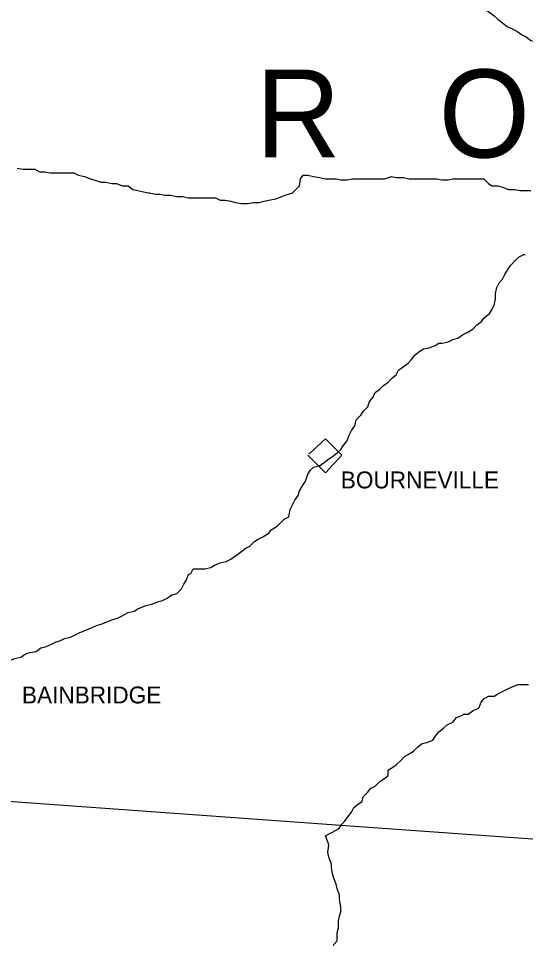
# Model space of a CAD drawing. Extents: x 0 to 40.2, y 0 to 22.
# Drawn here: x 5.119 to 5.704, y 18.331 to 19.393 of the extents above; entities that cross this region are included whole.
import ezdxf

# ---------------------------------------------------------------- set-up
doc = ezdxf.new("R2010")
doc.units = 0
doc.layers.add('Default', color=7, linetype='Continuous')
doc.layers.add('TR_Turning_Path1', color=7, linetype='Continuous')

msp = doc.modelspace()

# ---------------------------------------------------------------- linework, layer by layer
at = {"layer": 'Default'}
for points in [[(5.6558, 19.404), (5.6626, 19.3999), (5.668, 19.3958), (5.6721, 19.3917), (5.6776, 19.3876), (5.683, 19.3835), (5.6885, 19.3808), (5.6939, 19.3781), (5.6994, 19.374), (5.7048, 19.3713), (5.7103, 19.3672), (5.7157, 19.3658), (5.7212, 19.3631), (5.7267, 19.3617), (5.7321, 19.359), (5.7389, 19.3563), (5.7444, 19.3549), (5.7512, 19.3535), (5.758, 19.3535), (5.7621, 19.3522), (5.7621, 19.3522)], [(5.1172, 19.2199), (5.124, 19.2186), (5.1308, 19.2186), (5.1377, 19.2186), (5.1431, 19.2158), (5.1486, 19.2158), (5.1554, 19.2145), (5.1622, 19.2145), (5.1704, 19.2145), (5.1758, 19.2145), (5.1826, 19.2145), (5.1881, 19.2117), (5.1949, 19.2104), (5.2017, 19.2076), (5.2058, 19.2063), (5.214, 19.2036), (5.2195, 19.2036), (5.2263, 19.2022), (5.2317, 19.2022), (5.2385, 19.1995), (5.2454, 19.1995), (5.2508, 19.1954), (5.2563, 19.194), (5.2631, 19.1926), (5.2685, 19.1913), (5.2699, 19.1913)], [(5.3899, 19.1804), (5.3967, 19.1804), (5.4022, 19.1817), (5.4076, 19.1831), (5.4158, 19.1845), (5.4226, 19.1872), (5.4267, 19.1886), (5.4349, 19.1913), (5.439, 19.1954), (5.4431, 19.1995), (5.4444, 19.2076), (5.4472, 19.2117), (5.4526, 19.2117), (5.4594, 19.2104), (5.4662, 19.209), (5.4731, 19.2076), (5.4785, 19.2076), (5.4853, 19.2076), (5.4908, 19.2063), (5.4976, 19.2063), (5.5044, 19.2076), (5.5112, 19.2076), (5.5167, 19.2076), (5.5167, 19.2076)], [(5.5167, 19.2076), (5.5235, 19.2076), (5.5303, 19.2076), (5.5371, 19.2076), (5.5412, 19.2076), (5.5494, 19.2104), (5.5549, 19.209), (5.563, 19.209), (5.5699, 19.2076), (5.5767, 19.2076), (5.5821, 19.2076), (5.5889, 19.2076), (5.5958, 19.2076), (5.6012, 19.2076), (5.608, 19.2063), (5.6149, 19.2063), (5.6203, 19.2076), (5.6285, 19.2076), (5.6339, 19.2076), (5.6394, 19.2076), (5.6462, 19.2076), (5.6517, 19.2076), (5.6558, 19.2076), (5.6612, 19.2022), (5.6653, 19.1995), (5.6721, 19.1995), (5.6776, 19.1981), (5.6844, 19.1954), (5.6912, 19.1954), (5.698, 19.194), (5.7035, 19.194), (5.7103, 19.194)], [(5.2699, 19.1913), (5.2767, 19.1899), (5.2822, 19.1899), (5.2876, 19.1886), (5.2944, 19.1886), (5.3013, 19.1872), (5.3081, 19.1872), (5.3149, 19.1858), (5.3204, 19.1858), (5.3272, 19.1858), (5.334, 19.1858), (5.3394, 19.1858), (5.3463, 19.1858), (5.3517, 19.1831), (5.3572, 19.1831), (5.364, 19.1817), (5.3694, 19.1804), (5.3763, 19.179), (5.3831, 19.179), (5.3899, 19.1804), (5.3899, 19.1804)], [(5.608, 19.0181), (5.6149, 19.0195), (5.6203, 19.0222), (5.6258, 19.0236), (5.6312, 19.0277), (5.6367, 19.0304), (5.6435, 19.0345), (5.6476, 19.0386), (5.653, 19.0427), (5.6558, 19.0468), (5.6626, 19.0522), (5.6653, 19.0563), (5.668, 19.0618), (5.6694, 19.0686), (5.6694, 19.0754), (5.6708, 19.0822), (5.6735, 19.0877), (5.6776, 19.0918), (5.6803, 19.0972), (5.6844, 19.104), (5.6871, 19.1081), (5.6926, 19.1136), (5.6967, 19.1177), (5.7021, 19.1204), (5.7021, 19.1204), (5.7035, 19.1204)], [(5.4812, 18.8872), (5.4867, 18.8913), (5.4908, 18.8954), (5.4935, 18.8995), (5.4976, 18.905), (5.5003, 18.9118), (5.5031, 18.9172), (5.5071, 18.9227), (5.5085, 18.9295), (5.514, 18.935), (5.5167, 18.9391), (5.5221, 18.9445), (5.5235, 18.95), (5.5276, 18.9554), (5.5303, 18.9609), (5.5358, 18.965), (5.5399, 18.969), (5.5453, 18.9731), (5.5494, 18.9772), (5.5549, 18.9813), (5.5576, 18.9868), (5.563, 18.9909), (5.5685, 18.995), (5.5726, 18.999), (5.5767, 19.0045), (5.5821, 19.0086), (5.5862, 19.0113), (5.593, 19.0127), (5.5999, 19.0154), (5.6039, 19.0181), (5.608, 19.0181), (5.608, 19.0181)], [(5.4526, 18.8886), (5.4731, 18.8682), (5.4921, 18.8886), (5.4731, 18.9077), (5.454, 18.89)], [(5.3176, 18.7523), (5.3204, 18.7577), (5.3272, 18.7577), (5.334, 18.7577), (5.3408, 18.7591), (5.3449, 18.7618), (5.3517, 18.7645), (5.3585, 18.7659), (5.364, 18.7686), (5.3694, 18.7727), (5.3749, 18.7768), (5.3803, 18.7809), (5.3858, 18.7836), (5.3913, 18.7891), (5.3953, 18.7918), (5.4008, 18.7945), (5.4076, 18.7986), (5.4103, 18.8027), (5.4172, 18.8068), (5.4199, 18.8095), (5.4253, 18.815), (5.4308, 18.8177), (5.4322, 18.8259), (5.4349, 18.8313), (5.4376, 18.8368), (5.4417, 18.8422), (5.4431, 18.8477), (5.4472, 18.8545), (5.4499, 18.8586), (5.4526, 18.8668), (5.4553, 18.8709), (5.4594, 18.875), (5.4662, 18.8763), (5.4717, 18.8804), (5.4771, 18.8845), (5.4812, 18.8872), (5.4812, 18.8872)], [(5.2658, 18.7154), (5.2726, 18.7168), (5.2795, 18.7195), (5.2849, 18.7209), (5.2904, 18.7236), (5.2958, 18.7277), (5.3013, 18.7291), (5.3067, 18.7345), (5.3094, 18.74), (5.3122, 18.7441), (5.3149, 18.7509), (5.3176, 18.7523)], [(5.1663, 18.6745), (5.1717, 18.6773), (5.1786, 18.6786), (5.184, 18.6814), (5.1895, 18.6841), (5.1963, 18.6868), (5.2031, 18.6895), (5.2086, 18.6923), (5.214, 18.6936), (5.2208, 18.6964), (5.2276, 18.6991), (5.2331, 18.7005), (5.2385, 18.7032), (5.2454, 18.7073), (5.2522, 18.7086), (5.2563, 18.7114), (5.2631, 18.7141), (5.2658, 18.7154)], [(5.0763, 18.6432), (5.0818, 18.6459), (5.0886, 18.6473), (5.0954, 18.6486), (5.1022, 18.65), (5.1077, 18.6514), (5.1145, 18.6541), (5.1213, 18.6555), (5.1267, 18.6595), (5.1322, 18.6609), (5.139, 18.6623), (5.1445, 18.6664), (5.1499, 18.6677), (5.1567, 18.6705), (5.1622, 18.6732), (5.1663, 18.6745), (5.1663, 18.6745)], [(5.6339, 18.59), (5.638, 18.59), (5.6435, 18.5941), (5.6503, 18.5968), (5.653, 18.6036), (5.6558, 18.6077), (5.6612, 18.6105), (5.668, 18.6105), (5.6721, 18.6132), (5.6776, 18.6159), (5.683, 18.6186), (5.6885, 18.6214), (5.6953, 18.6241), (5.7021, 18.6241), (5.7076, 18.6241)], [(5.5467, 18.5259), (5.5508, 18.5287), (5.5549, 18.5314), (5.5603, 18.5368), (5.5644, 18.5409), (5.5712, 18.545), (5.5753, 18.5477), (5.5794, 18.5518), (5.5849, 18.5559), (5.5903, 18.5573), (5.5971, 18.56), (5.5999, 18.5641), (5.6039, 18.5696), (5.6094, 18.5737), (5.6135, 18.5777), (5.6203, 18.5805), (5.6244, 18.5859), (5.6312, 18.5887), (5.6326, 18.59), (5.6339, 18.59)], [(5.4908, 18.4619), (5.4949, 18.4659), (5.499, 18.4714), (5.5031, 18.4769), (5.5058, 18.4823), (5.5112, 18.4864), (5.5153, 18.4891), (5.5167, 18.4946), (5.5221, 18.5), (5.5249, 18.5041), (5.5303, 18.5068), (5.5358, 18.5123), (5.5399, 18.515), (5.5453, 18.5191), (5.5453, 18.5246), (5.5467, 18.5259)], [(4.7818, 18.5109), (4.9195, 18.5028), (5.4908, 18.4619), (6.122, 18.4169), (6.7819, 18.3678)], [(5.4867, 18.3378), (5.4881, 18.3432), (5.4881, 18.3514), (5.4894, 18.3569), (5.4908, 18.3623), (5.4908, 18.3678), (5.4894, 18.376), (5.4894, 18.3814), (5.4867, 18.3882), (5.4853, 18.3937), (5.4826, 18.4005), (5.4812, 18.406), (5.4799, 18.4128), (5.4799, 18.4169), (5.4771, 18.425), (5.4758, 18.4305), (5.4771, 18.4387), (5.4758, 18.4428), (5.4731, 18.4496), (5.4758, 18.4509), (5.4812, 18.4537), (5.4881, 18.4578), (5.4908, 18.4605), (5.4908, 18.4619)], [(5.5167, 18.2546), (5.514, 18.2614), (5.5085, 18.2669), (5.5058, 18.271), (5.5031, 18.2764), (5.5003, 18.2819), (5.499, 18.2873), (5.4949, 18.2928), (5.4894, 18.2928), (5.4881, 18.2996), (5.4867, 18.3051), (5.484, 18.3105), (5.4812, 18.3173), (5.4826, 18.3241), (5.4867, 18.3282), (5.4867, 18.3351), (5.4867, 18.3378)]]:
    msp.add_lwpolyline(points, dxfattribs=at)

# ---------------------------------------------------------------- texts
for s, height, p in [('BOURNEVILLE', 0.019502, (5.4908, 18.8504)), ('BAINBRIDGE', 0.0195, (5.1227, 18.6023))]:
    msp.add_text(s, height=height, dxfattribs=at).set_placement(p)
at = {"layer": 'TR_Turning_Path1'}
msp.add_text('R   O    S   S', height=0.101489, dxfattribs=at).set_placement((5.3926, 19.2322))

doc.saveas('drawing.dxf')
